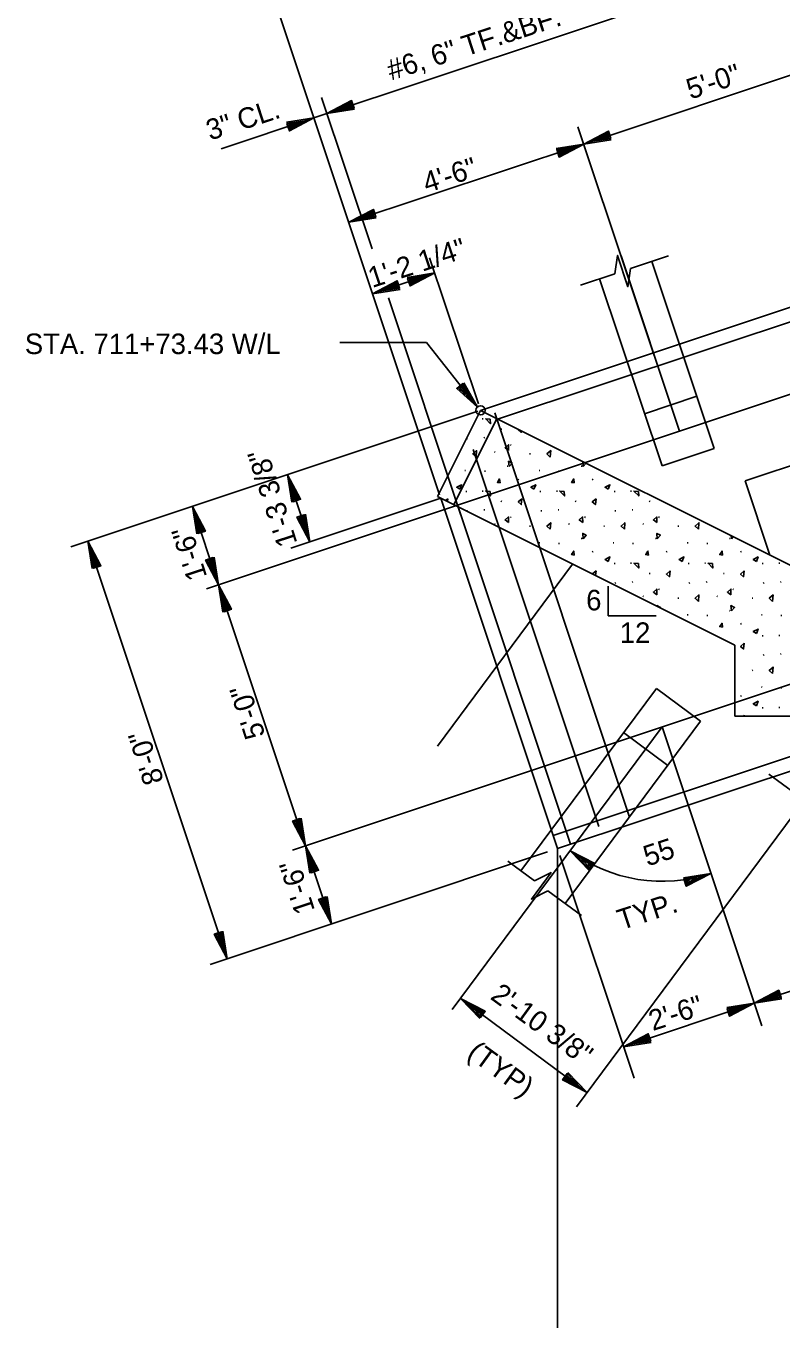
# Model space of a CAD drawing. Extents: x 6 to 106, y 3 to 74.
# Drawn here: x 6.3 to 20.04, y 35.87 to 59.54 of the extents above; entities that cross this region are included whole.
import ezdxf

# ---------------------------------------------------------------- set-up
doc = ezdxf.new("R2010")
doc.units = 0
for name, color, linetype in [('Level 13', 7, 'Continuous'), ('Level 22', 7, 'Continuous'), ('Level 25', 7, 'Continuous'), ('Level 44', 7, 'Continuous'), ('Level 50', 7, 'Continuous')]:
    doc.layers.add(name, color=color, linetype=linetype)

msp = doc.modelspace()

# ---------------------------------------------------------------- linework, layer by layer
at = {"layer": 'Level 13'}
for points in [[(17.003, 55.035), (17.05, 55.367), (17.239, 54.798), (17.287, 55.13)], [(15.544, 43.997), (15.843, 44.149), (15.486, 43.668), (15.784, 43.819)]]:
    msp.add_lwpolyline(points, dxfattribs=at)
at = {"layer": 'Level 22'}
for p, q in [((13.577, 53.786), (14.503, 52.611)), ((14.561, 52.551), (13.778, 50.985)), ((21.163, 49.25), (14.561, 52.551)), ((14.859, 52.401), (14.076, 50.836)), ((19.18, 48.284), (13.778, 50.985)), ((13.778, 46.448), (16.233, 49.758)), ((16.877, 48.815), (16.877, 49.353)), ((16.877, 48.815), (17.749, 48.815)), ((16.306, 39.892), (22.602, 48.379)), ((15.295, 44.181), (17.755, 47.498)), ((18.558, 46.902), (17.755, 47.498)), ((16.098, 43.586), (18.558, 46.902)), ((14.047, 41.659), (17.859, 46.798)), ((17.962, 46.099), (17.159, 46.695)), ((20.293, 45.574), (19.797, 45.941)), ((15.544, 43.997), (15.054, 44.36)), ((16.394, 43.367), (15.784, 43.819)), ((16.499, 40.152), (14.196, 41.86))]:
    msp.add_line(p, q, dxfattribs=at)
msp.add_circle((14.561, 52.551), 0.0833, dxfattribs=at)
msp.add_arc((17.859, 46.798), 2.806, 233.435, 288.4344, dxfattribs=at)
at = {"layer": 'Level 25'}
for p, q in [((14.561, 52.551), (41.18, 61.424)), ((11.534, 57.866), (21.258, 61.108)), ((14.835, 52.378), (41.18, 61.16)), ((13.817, 51.018), (10.789, 60.1)), ((9.584, 49.31), (41.18, 59.843)), ((16.436, 57.392), (21.179, 58.973)), ((12.59, 55.489), (11.673, 58.239)), ((9.85, 57.305), (11.534, 57.866)), ((18.175, 52.174), (16.331, 57.707)), ((12.167, 55.969), (16.436, 57.392)), ((14.521, 52.67), (13.636, 55.323)), ((18.175, 52.174), (17.113, 55.36)), ((17.287, 55.13), (17.973, 55.358)), ((18.807, 51.858), (17.674, 55.259)), ((12.599, 54.672), (13.728, 55.048)), ((16.375, 54.826), (17.003, 55.035)), ((17.859, 51.542), (16.725, 54.942)), ((11.145, 44.56), (41.18, 54.572)), ((14.204, 50.648), (12.887, 54.599)), ((12.006, 53.786), (13.577, 53.786)), ((15.882, 44.822), (41.18, 53.255)), ((15.961, 44.585), (41.18, 52.991)), ((17.542, 52.49), (18.491, 52.807)), ((7.116, 50.069), (14.511, 52.534)), ((17.27, 45.158), (14.82, 52.507)), ((16.711, 44.989), (14.428, 51.838)), ((17.859, 51.542), (18.807, 51.858)), ((19.368, 51.269), (21.443, 51.961)), ((11.461, 50.163), (11.054, 51.382)), ((19.817, 49.922), (19.368, 51.269)), ((11.116, 50.048), (13.838, 50.955)), ((15.961, 44.585), (13.838, 50.955)), ((9.8, 49.382), (9.325, 50.805)), ((16.198, 44.664), (14.135, 50.853)), ((9.958, 42.584), (7.428, 50.173)), ((11.381, 44.639), (9.8, 49.382)), ((19.18, 46.991), (19.18, 48.284)), ((19.18, 46.991), (23.18, 46.991)), ((19.67, 41.363), (17.859, 46.798)), ((9.651, 42.481), (15.78, 44.524)), ((11.855, 43.216), (11.381, 44.639)), ((17.352, 40.411), (16.002, 44.462)), ((19.533, 41.775), (24.276, 43.356)), ((17.161, 40.985), (19.533, 41.775))]:
    msp.add_line(p, q, dxfattribs=at)
at = {"layer": 'Level 44'}
for p, q in [((14.61, 52.395), (14.593, 52.395)), ((14.949, 52.209), (14.932, 52.212)), ((14.325, 52.04), (14.307, 52.035)), ((14.636, 52.058), (14.623, 52.053)), ((15.119, 51.917), (15.104, 51.926)), ((14.828, 51.793), (14.814, 51.799)), ((15.468, 51.761), (15.453, 51.759)), ((14.29, 51.456), (14.276, 51.458)), ((14.648, 51.444), (14.63, 51.444)), ((15.059, 51.534), (15.045, 51.535)), ((15.636, 51.456), (15.623, 51.458)), ((15.995, 51.444), (15.977, 51.444)), ((16.405, 51.534), (16.392, 51.535)), ((15.259, 51.299), (15.243, 51.291)), ((16.606, 51.299), (16.59, 51.291)), ((14.311, 51.077), (14.293, 51.077)), ((14.61, 51.084), (14.593, 51.084)), ((14.949, 50.897), (14.932, 50.9)), ((15.658, 51.077), (15.64, 51.077)), ((15.956, 51.084), (15.939, 51.084)), ((16.296, 50.897), (16.278, 50.9)), ((17.004, 51.077), (16.986, 51.077)), ((17.303, 51.084), (17.286, 51.084)), ((17.642, 50.897), (17.625, 50.9)), ((14.325, 50.728), (14.307, 50.723)), ((14.636, 50.746), (14.623, 50.741)), ((15.672, 50.728), (15.654, 50.723)), ((15.983, 50.746), (15.97, 50.741)), ((17.019, 50.728), (17.001, 50.723)), ((17.329, 50.746), (17.316, 50.741)), ((14.828, 50.481), (14.814, 50.488)), ((15.119, 50.605), (15.104, 50.614)), ((15.468, 50.449), (15.453, 50.448)), ((16.175, 50.481), (16.161, 50.488)), ((16.465, 50.605), (16.45, 50.614)), ((16.815, 50.449), (16.8, 50.448)), ((17.522, 50.481), (17.507, 50.488)), ((17.812, 50.605), (17.797, 50.614)), ((18.161, 50.449), (18.147, 50.448)), ((16.405, 50.222), (16.392, 50.223)), ((17.752, 50.222), (17.739, 50.223)), ((19.099, 50.222), (19.085, 50.223)), ((15.636, 50.144), (15.623, 50.146)), ((15.995, 50.133), (15.977, 50.133)), ((16.606, 49.987), (16.59, 49.979)), ((16.983, 50.144), (16.97, 50.146)), ((17.342, 50.133), (17.324, 50.133)), ((17.952, 49.987), (17.936, 49.979)), ((18.33, 50.144), (18.316, 50.146)), ((18.688, 50.133), (18.67, 50.133)), ((19.299, 49.987), (19.283, 49.979)), ((17.004, 49.766), (16.986, 49.766)), ((17.303, 49.772), (17.286, 49.772)), ((18.351, 49.766), (18.333, 49.766)), ((18.65, 49.772), (18.633, 49.772)), ((19.698, 49.766), (19.68, 49.766)), ((19.996, 49.772), (19.979, 49.772)), ((17.642, 49.586), (17.625, 49.589)), ((18.989, 49.586), (18.972, 49.589)), ((17.019, 49.417), (17.001, 49.412)), ((17.329, 49.435), (17.316, 49.43)), ((17.812, 49.293), (17.797, 49.302)), ((18.365, 49.417), (18.347, 49.412)), ((18.676, 49.435), (18.663, 49.43)), ((19.159, 49.293), (19.144, 49.302)), ((19.712, 49.417), (19.694, 49.412)), ((20.023, 49.435), (20.01, 49.43)), ((17.522, 49.169), (17.507, 49.176)), ((18.161, 49.137), (18.147, 49.136)), ((18.868, 49.169), (18.854, 49.176)), ((19.508, 49.137), (19.493, 49.136)), ((18.33, 48.832), (18.316, 48.835)), ((18.688, 48.821), (18.67, 48.821)), ((19.099, 48.91), (19.085, 48.911)), ((19.676, 48.832), (19.663, 48.835)), ((20.035, 48.821), (20.017, 48.821)), ((19.299, 48.675), (19.283, 48.667)), ((19.698, 48.454), (19.68, 48.454)), ((19.996, 48.46), (19.979, 48.46)), ((19.712, 48.105), (19.694, 48.1)), ((20.023, 48.123), (20.01, 48.118)), ((19.508, 47.826), (19.493, 47.824)), ((19.299, 47.364), (19.283, 47.356)), ((19.676, 47.521), (19.663, 47.523)), ((20.035, 47.509), (20.017, 47.509)), ((19.698, 47.142), (19.68, 47.142)), ((19.996, 47.149), (19.979, 47.149)), ((15.961, 44.585), (15.961, 35.873))]:
    msp.add_line(p, q, dxfattribs=at)
for points in [[(14.735, 52.391), (14.655, 52.395), (14.741, 52.307)], [(15.071, 51.822), (15.007, 51.871), (15.069, 51.925)], [(14.482, 51.702), (14.42, 51.759), (14.488, 51.82)], [(15.078, 51.529), (15.135, 51.593), (15.071, 51.627)], [(15.828, 51.702), (15.767, 51.759), (15.835, 51.82)], [(14.185, 51.116), (14.217, 51.198), (14.128, 51.155)], [(14.918, 51.231), (14.908, 51.304), (14.867, 51.243)], [(15.532, 51.116), (15.563, 51.198), (15.475, 51.155)], [(16.264, 51.231), (16.255, 51.304), (16.214, 51.243)], [(16.878, 51.116), (16.91, 51.198), (16.822, 51.155)], [(14.735, 51.079), (14.655, 51.084), (14.741, 50.995)], [(15.313, 50.945), (15.245, 50.886), (15.301, 50.838)], [(16.081, 51.079), (16.001, 51.084), (16.088, 50.995)], [(16.66, 50.945), (16.591, 50.886), (16.648, 50.838)], [(17.428, 51.079), (17.348, 51.084), (17.435, 50.995)], [(15.071, 50.511), (15.007, 50.559), (15.069, 50.613)], [(15.828, 50.39), (15.767, 50.447), (15.835, 50.508)], [(16.418, 50.511), (16.354, 50.559), (16.415, 50.613)], [(17.175, 50.39), (17.113, 50.447), (17.182, 50.508)], [(17.765, 50.511), (17.701, 50.559), (17.762, 50.613)], [(18.522, 50.39), (18.46, 50.447), (18.528, 50.508)], [(16.425, 50.217), (16.482, 50.281), (16.418, 50.315)], [(17.771, 50.217), (17.828, 50.281), (17.765, 50.315)], [(16.264, 49.919), (16.255, 49.992), (16.214, 49.931)], [(17.611, 49.919), (17.602, 49.992), (17.561, 49.931)], [(18.958, 49.919), (18.948, 49.992), (18.907, 49.931)], [(16.878, 49.805), (16.91, 49.886), (16.822, 49.843)], [(17.428, 49.768), (17.348, 49.772), (17.435, 49.683)], [(18.225, 49.805), (18.257, 49.886), (18.168, 49.843)], [(18.775, 49.768), (18.695, 49.772), (18.781, 49.683)], [(19.572, 49.805), (19.603, 49.886), (19.515, 49.843)], [(18.006, 49.634), (17.938, 49.574), (17.995, 49.526)], [(19.353, 49.634), (19.285, 49.574), (19.341, 49.526)], [(17.765, 49.199), (17.701, 49.247), (17.762, 49.302)], [(19.111, 49.199), (19.047, 49.247), (19.109, 49.302)], [(18.522, 49.079), (18.46, 49.136), (18.528, 49.197)], [(19.118, 48.906), (19.175, 48.97), (19.111, 49.004)], [(19.868, 49.079), (19.807, 49.136), (19.875, 49.197)], [(18.958, 48.608), (18.948, 48.681), (18.907, 48.62)], [(19.572, 48.493), (19.603, 48.575), (19.515, 48.532)], [(19.353, 48.322), (19.285, 48.262), (19.341, 48.215)], [(19.868, 47.767), (19.807, 47.824), (19.875, 47.885)], [(19.572, 47.181), (19.603, 47.263), (19.515, 47.22)]]:
    msp.add_lwpolyline(points, close=True, dxfattribs=at)
for points in [[(15.253, 52.204), (15.245, 52.197), (15.301, 52.15), (15.305, 52.179)], [(16.419, 51.622), (16.425, 51.529)], [(16.425, 51.529), (16.48, 51.591)], [(13.966, 50.945), (13.927, 50.911)], [(13.961, 50.894), (13.966, 50.945)], [(19.114, 50.274), (19.118, 50.217)], [(19.118, 50.217), (19.152, 50.255)], [(16.66, 49.634), (16.595, 49.577)], [(16.651, 49.549), (16.66, 49.634)], [(17.823, 48.963), (17.828, 48.97), (17.765, 49.004), (17.766, 48.991)], [(19.353, 47.01), (19.331, 46.991)], [(19.351, 46.991), (19.353, 47.01)]]:
    msp.add_lwpolyline(points, dxfattribs=at)
at = {"layer": 'Level 50'}
for p, q in [((11.903, 57.989), (11.903, 57.989)), ((11.403, 57.822), (11.403, 57.822)), ((11.534, 57.866), (11.534, 57.866)), ((11.771, 57.945), (11.771, 57.945)), ((16.304, 57.348), (16.304, 57.348)), ((16.436, 57.392), (16.436, 57.392)), ((16.436, 57.392), (16.436, 57.392)), ((16.567, 57.436), (16.567, 57.436)), ((12.167, 55.969), (12.167, 55.969)), ((12.298, 56.013), (12.298, 56.013)), ((13.597, 55.004), (13.597, 55.004)), ((13.728, 55.048), (13.728, 55.048)), ((12.599, 54.672), (12.599, 54.672)), ((12.731, 54.716), (12.731, 54.716)), ((14.417, 52.72), (14.417, 52.72)), ((14.503, 52.611), (14.503, 52.611)), ((11.054, 51.382), (11.054, 51.382)), ((11.098, 51.25), (11.098, 51.25)), ((9.325, 50.805), (9.325, 50.805)), ((9.369, 50.674), (9.369, 50.674)), ((7.428, 50.173), (7.428, 50.173)), ((11.417, 50.295), (11.417, 50.295)), ((7.472, 50.041), (7.472, 50.041)), ((11.461, 50.163), (11.461, 50.163)), ((9.756, 49.514), (9.756, 49.514)), ((9.8, 49.382), (9.8, 49.382)), ((9.8, 49.382), (9.8, 49.382)), ((9.8, 49.382), (9.8, 49.382)), ((9.843, 49.251), (9.843, 49.251)), ((9.843, 49.251), (9.843, 49.251)), ((11.337, 44.771), (11.337, 44.771)), ((11.381, 44.639), (11.381, 44.639)), ((11.381, 44.639), (11.381, 44.639)), ((11.381, 44.639), (11.381, 44.639)), ((11.425, 44.507), (11.425, 44.507)), ((11.425, 44.507), (11.425, 44.507)), ((16.187, 44.544), (16.187, 44.544)), ((16.187, 44.544), (16.187, 44.544)), ((16.298, 44.462), (16.298, 44.462)), ((16.298, 44.462), (16.298, 44.462)), ((18.614, 44.092), (18.614, 44.092)), ((18.614, 44.092), (18.614, 44.092)), ((18.746, 44.136), (18.746, 44.136)), ((18.746, 44.136), (18.746, 44.136)), ((11.811, 43.348), (11.811, 43.348)), ((11.855, 43.216), (11.855, 43.216)), ((9.914, 42.715), (9.914, 42.715)), ((9.914, 42.715), (9.914, 42.715)), ((9.958, 42.584), (9.958, 42.584)), ((9.958, 42.584), (9.958, 42.584)), ((14.196, 41.86), (14.196, 41.86)), ((14.307, 41.778), (14.307, 41.778)), ((19.401, 41.731), (19.401, 41.731)), ((19.533, 41.775), (19.533, 41.775)), ((19.533, 41.775), (19.533, 41.775)), ((19.665, 41.819), (19.665, 41.819)), ((17.161, 40.985), (17.161, 40.985)), ((17.293, 41.029), (17.293, 41.029)), ((16.388, 40.234), (16.388, 40.234)), ((16.499, 40.152), (16.499, 40.152))]:
    msp.add_line(p, q, dxfattribs=at)
for points in [[(12.27, 58.025), (11.771, 57.945), (12.218, 58.181), (12.263, 58.047), (11.903, 57.989), (12.206, 58.149), (12.235, 58.063), (12.029, 58.031), (12.195, 58.117), (12.206, 58.082), (12.161, 58.075)], [(11.035, 57.787), (11.534, 57.866), (11.087, 57.63), (11.042, 57.764), (11.403, 57.822), (11.099, 57.662), (11.07, 57.748), (11.276, 57.78), (11.111, 57.694), (11.099, 57.73), (11.145, 57.736)], [(16.935, 57.471), (16.436, 57.392), (16.883, 57.628), (16.927, 57.494), (16.567, 57.436), (16.871, 57.596), (16.899, 57.51), (16.694, 57.478), (16.859, 57.564), (16.871, 57.529), (16.825, 57.522)], [(15.936, 57.313), (16.436, 57.392), (15.989, 57.156), (15.944, 57.29), (16.304, 57.348), (16.001, 57.188), (15.972, 57.274), (16.178, 57.306), (16.012, 57.22), (16.001, 57.255), (16.046, 57.262)], [(12.666, 56.048), (12.167, 55.969), (12.614, 56.205), (12.658, 56.071), (12.298, 56.013), (12.602, 56.173), (12.63, 56.087), (12.425, 56.055), (12.59, 56.141), (12.602, 56.106), (12.556, 56.099)], [(13.098, 54.751), (12.599, 54.672), (13.046, 54.908), (13.091, 54.774), (12.731, 54.716), (13.034, 54.876), (13.063, 54.79), (12.857, 54.758), (13.022, 54.844), (13.034, 54.808), (12.989, 54.802)], [(13.229, 54.969), (13.728, 55.048), (13.281, 54.812), (13.236, 54.946), (13.597, 55.004), (13.293, 54.844), (13.264, 54.93), (13.47, 54.962), (13.305, 54.876), (13.293, 54.911), (13.338, 54.918)], [(14.259, 53.054), (14.503, 52.611), (14.129, 52.951), (14.24, 53.039), (14.417, 52.72), (14.164, 52.951), (14.235, 53.007), (14.335, 52.824), (14.198, 52.951), (14.227, 52.974), (14.249, 52.933)], [(11.134, 50.883), (11.054, 51.382), (11.291, 50.935), (11.156, 50.89), (11.098, 51.25), (11.259, 50.947), (11.173, 50.918), (11.14, 51.124), (11.226, 50.959), (11.191, 50.947), (11.184, 50.992)], [(9.405, 50.306), (9.325, 50.805), (9.561, 50.358), (9.427, 50.314), (9.369, 50.674), (9.529, 50.37), (9.443, 50.342), (9.411, 50.547), (9.497, 50.382), (9.462, 50.37), (9.455, 50.416)], [(11.381, 50.662), (11.461, 50.163), (11.225, 50.61), (11.359, 50.655), (11.417, 50.295), (11.257, 50.598), (11.343, 50.627), (11.375, 50.421), (11.289, 50.586), (11.324, 50.598), (11.331, 50.553)], [(7.507, 49.674), (7.428, 50.173), (7.664, 49.726), (7.53, 49.681), (7.472, 50.041), (7.632, 49.738), (7.546, 49.709), (7.514, 49.915), (7.6, 49.75), (7.565, 49.738), (7.558, 49.783)], [(9.72, 49.882), (9.8, 49.382), (9.564, 49.829), (9.698, 49.874), (9.756, 49.514), (9.596, 49.818), (9.682, 49.846), (9.714, 49.64), (9.628, 49.806), (9.663, 49.818), (9.67, 49.772)], [(9.879, 48.883), (9.8, 49.382), (10.036, 48.935), (9.902, 48.891), (9.843, 49.251), (10.004, 48.947), (9.918, 48.919), (9.886, 49.124), (9.972, 48.959), (9.936, 48.947), (9.929, 48.993)], [(9.879, 48.883), (9.8, 49.382), (10.036, 48.935), (9.902, 48.891), (9.843, 49.251), (10.004, 48.947), (9.918, 48.919), (9.886, 49.124), (9.972, 48.959), (9.936, 48.947), (9.929, 48.993)], [(11.301, 45.138), (11.381, 44.639), (11.145, 45.086), (11.279, 45.131), (11.337, 44.771), (11.177, 45.074), (11.263, 45.103), (11.295, 44.897), (11.209, 45.062), (11.244, 45.074), (11.251, 45.029)], [(11.46, 44.14), (11.381, 44.639), (11.617, 44.192), (11.483, 44.147), (11.425, 44.507), (11.585, 44.204), (11.499, 44.175), (11.467, 44.381), (11.553, 44.216), (11.517, 44.204), (11.511, 44.249)], [(11.46, 44.14), (11.381, 44.639), (11.617, 44.192), (11.483, 44.147), (11.425, 44.507), (11.585, 44.204), (11.499, 44.175), (11.467, 44.381), (11.553, 44.216), (11.517, 44.204), (11.511, 44.249)], [(16.538, 44.181), (16.187, 44.544), (16.637, 44.314), (16.553, 44.2), (16.298, 44.462), (16.604, 44.305), (16.55, 44.232), (16.405, 44.382), (16.571, 44.296), (16.548, 44.266), (16.517, 44.3)], [(16.538, 44.181), (16.187, 44.544), (16.637, 44.314), (16.553, 44.2), (16.298, 44.462), (16.604, 44.305), (16.55, 44.232), (16.405, 44.382), (16.571, 44.296), (16.548, 44.266), (16.517, 44.3)], [(18.247, 44.057), (18.746, 44.136), (18.299, 43.9), (18.254, 44.034), (18.614, 44.092), (18.311, 43.932), (18.282, 44.018), (18.488, 44.05), (18.323, 43.964), (18.311, 44), (18.356, 44.006)], [(18.247, 44.057), (18.746, 44.136), (18.299, 43.9), (18.254, 44.034), (18.614, 44.092), (18.311, 43.932), (18.282, 44.018), (18.488, 44.05), (18.323, 43.964), (18.311, 44), (18.356, 44.006)], [(11.776, 43.715), (11.855, 43.216), (11.619, 43.663), (11.753, 43.708), (11.811, 43.348), (11.651, 43.651), (11.737, 43.68), (11.769, 43.474), (11.683, 43.639), (11.718, 43.651), (11.725, 43.606)], [(9.878, 43.083), (9.958, 42.584), (9.722, 43.03), (9.856, 43.075), (9.914, 42.715), (9.754, 43.019), (9.84, 43.047), (9.872, 42.842), (9.786, 43.007), (9.821, 43.019), (9.828, 42.973)], [(9.878, 43.083), (9.958, 42.584), (9.722, 43.03), (9.856, 43.075), (9.914, 42.715), (9.754, 43.019), (9.84, 43.047), (9.872, 42.842), (9.786, 43.007), (9.821, 43.019), (9.828, 42.973)], [(20.032, 41.855), (19.533, 41.775), (19.98, 42.011), (20.025, 41.877), (19.665, 41.819), (19.968, 41.979), (19.997, 41.893), (19.791, 41.861), (19.956, 41.947), (19.968, 41.912), (19.923, 41.905)], [(14.547, 41.497), (14.196, 41.86), (14.646, 41.63), (14.562, 41.516), (14.307, 41.778), (14.613, 41.621), (14.559, 41.548), (14.415, 41.698), (14.58, 41.612), (14.558, 41.582), (14.526, 41.616)], [(19.034, 41.696), (19.533, 41.775), (19.086, 41.539), (19.041, 41.673), (19.401, 41.731), (19.098, 41.571), (19.069, 41.657), (19.275, 41.689), (19.11, 41.603), (19.098, 41.639), (19.143, 41.645)], [(17.661, 41.064), (17.161, 40.985), (17.608, 41.221), (17.653, 41.087), (17.293, 41.029), (17.596, 41.189), (17.625, 41.103), (17.419, 41.071), (17.585, 41.157), (17.596, 41.121), (17.551, 41.115)], [(16.148, 40.515), (16.499, 40.152), (16.05, 40.382), (16.134, 40.496), (16.388, 40.234), (16.083, 40.391), (16.137, 40.464), (16.281, 40.314), (16.116, 40.4), (16.138, 40.43), (16.17, 40.396)]]:
    msp.add_lwpolyline(points, dxfattribs=at)

# ---------------------------------------------------------------- texts
at = {"layer": 'Level 22'}
for s, height, rotation, p in [('#6, 6" TF.&BF. + 10\'-3"', 0.37333, 18, (12.936, 58.543)), ('5\'-0"', 0.3733, 18, (18.374, 58.2)), ('3" CL.', 0.3733, 18, (9.648, 57.454)), ('4\'-6"', 0.3733, 18, (13.585, 56.5)), ('1\'-2 1/4"', 0.3733, 18, (12.592, 54.774)), ('1\'-3 3/8"', 0.3733, 108, (11.237, 50.141)), ('1\'-6"', 0.3733, 108, (9.598, 49.529)), ('5\'-0"', 0.3733, 108, (10.654, 46.648)), ('8\'-0"', 0.3733, 108, (8.811, 45.816)), ('55', 0.3733, 18, (17.592, 44.26)), ('1\'-6"', 0.3733, 108, (11.556, 43.465)), ('TYP.', 0.3733, 18, (17.119, 43.102)), ('2\'-10 3/8"', 0.3733, 324, (14.72, 41.864)), ('2\'-6"', 0.3733, 18, (17.69, 41.268)), ('(TYP)', 0.3733, 324, (14.295, 40.812))]:
    msp.add_text(s, height=height, rotation=rotation, dxfattribs=at).set_placement(p)
for s, height, p in [('STA. 711+73.43 W/L', 0.37333, (6.281, 53.574)), ('6', 0.373, (16.48, 48.916)), ('12', 0.3733, (17.091, 48.324))]:
    msp.add_text(s, height=height, dxfattribs=at).set_placement(p)

doc.saveas('drawing.dxf')
